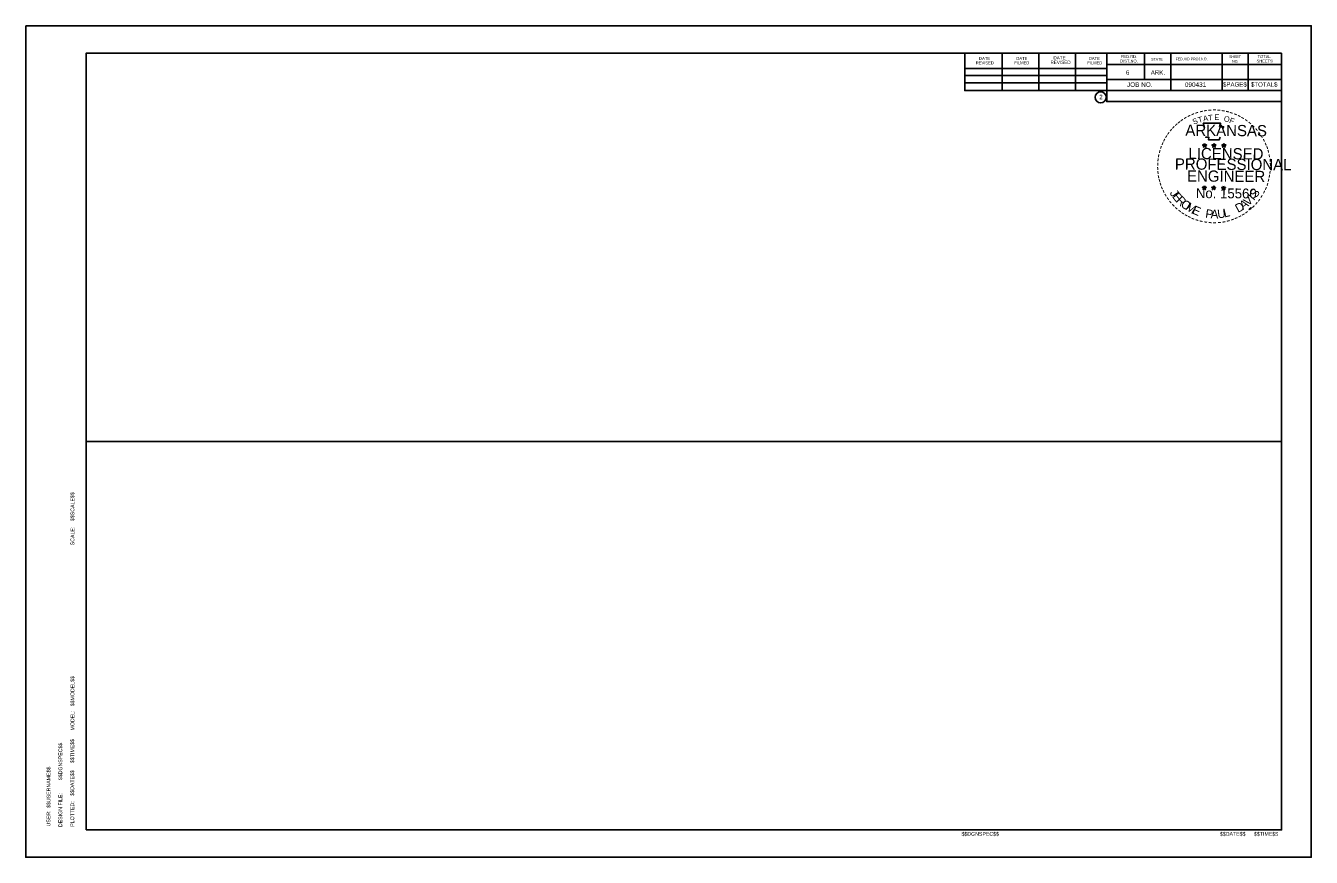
# Model space of a CAD drawing. Extents: x -1.6 to 32.4, y -0.7 to 21.3.
import ezdxf

# ---------------------------------------------------------------- set-up
doc = ezdxf.new("R2010")
doc.units = 0
for name, color, linetype in [('Level 1', 7, 'Continuous'), ('Level 24', 7, 'Continuous'), ('Level 37', 7, 'Continuous'), ('Level 48', 7, 'Continuous'), ('Level 62', 7, 'Continuous'), ('Level 63', 7, 'Continuous'), ('R_Border Prelim', 7, 'Continuous')]:
    doc.layers.add(name, color=color, linetype=linetype)

msp = doc.modelspace()

# ---------------------------------------------------------------- linework, layer by layer
at = {"layer": 'Level 1'}
for p, q in [((-0.001, 20.545), (31.617, 20.545)), ((-0.001, -0.001), (-0.001, 20.545)), ((23.238, 19.557), (23.238, 20.545)), ((24.224, 19.557), (24.224, 20.525)), ((25.2, 19.557), (25.2, 20.525)), ((26.168, 19.557), (26.168, 20.525)), ((26.994, 20.545), (26.994, 19.557)), ((27.991, 20.545), (27.991, 19.851)), ((28.685, 20.545), (28.685, 19.557)), ((30.043, 20.545), (30.043, 19.557)), ((30.737, 20.545), (30.737, 19.557)), ((31.617, -0.001), (31.617, 20.545)), ((23.238, 20.143), (26.994, 20.143)), ((31.617, 20.251), (26.994, 20.251)), ((31.617, 20.253), (31.617, 20.253)), ((23.238, 19.957), (26.994, 19.957)), ((23.238, 19.763), (26.994, 19.763)), ((31.617, 19.851), (26.994, 19.851)), ((27.603, 19.851), (31.617, 19.851)), ((31.617, 19.557), (23.238, 19.557)), ((26.994, 19.557), (26.994, 19.265)), ((26.994, 19.265), (31.617, 19.265)), ((31.617, -0.001), (-0.001, -0.001))]:
    msp.add_line(p, q, dxfattribs=at)
msp.add_circle((26.833, 19.379), 0.147, dxfattribs=at)
at = {"layer": 'Level 24'}
for p, q in [((-0.001, 20.545), (-0.001, -0.001)), ((23.238, 19.557), (23.238, 20.545)), ((26.999, 19.557), (23.238, 19.557)), ((26.994, 19.265), (26.994, 19.557)), ((26.994, 19.557), (26.999, 19.557)), ((31.617, 19.265), (26.994, 19.265)), ((26.994, 19.265), (26.994, 19.265)), ((31.617, -0.001), (31.617, 19.265)), ((-0.001, -0.001), (31.617, -0.001))]:
    msp.add_line(p, q, dxfattribs=at)
msp.add_lwpolyline([(23.238, 20.545), (23.391, 20.545), (23.391, 20.545), (-0.001, 20.545)], dxfattribs=at)
at = {"layer": 'Level 37'}
for p, q in [((-0.002, 10.755), (-0.001, 20.545)), ((-0.001, 20.545), (31.617, 20.545)), ((31.617, 20.545), (31.617, 10.273)), ((-0.001, 10.273), (-0.002, 10.755)), ((-0.002, 10.755), (-0.002, 10.755)), ((-0.002, 0.481), (-0.001, 10.271)), ((-0.002, 0.481), (-0.001, 10.271)), ((31.617, 10.273), (-0.001, 10.273)), ((-0.001, 10.271), (31.617, 10.271)), ((-0.001, 10.271), (31.617, 10.271)), ((31.617, 10.271), (31.617, -0.001)), ((31.617, 10.271), (31.617, -0.001)), ((-0.001, -0.001), (-0.002, 0.481)), ((-0.002, 0.481), (-0.002, 0.481)), ((-0.001, -0.001), (-0.002, 0.481)), ((-0.002, 0.481), (-0.002, 0.481)), ((31.617, -0.001), (-0.001, -0.001)), ((31.617, -0.001), (-0.001, -0.001))]:
    msp.add_line(p, q, dxfattribs=at)
at = {"layer": 'Level 62'}
msp.add_lwpolyline([(-0.001, -0.001), (31.617, -0.001), (31.617, 19.265), (26.994, 19.265), (26.994, 19.557), (27.307, 19.557), (26.999, 19.557), (23.238, 19.557), (23.238, 20.545), (23.391, 20.545), (23.391, 20.545), (-0.001, 20.545)], close=True, dxfattribs=at)
at = {"layer": 'Level 63'}
msp.add_lwpolyline([(-1.598, 21.273), (32.402, 21.273), (32.402, -0.727), (-1.598, -0.727)], close=True, dxfattribs=at)
at = {"layer": 'R_Border Prelim'}
for p, q in [((29.529, 18.121), (29.582, 18.105)), ((29.529, 18.121), (29.567, 18.119)), ((29.529, 18.121), (29.567, 18.117)), ((29.529, 18.121), (29.564, 18.112)), ((29.529, 18.121), (29.564, 18.106)), ((29.529, 18.121), (29.564, 18.105)), ((29.529, 18.121), (29.564, 18.099)), ((29.551, 18.061), (29.582, 18.105)), ((29.551, 18.061), (29.564, 18.103)), ((29.551, 18.061), (29.567, 18.097)), ((29.551, 18.061), (29.569, 18.095)), ((29.551, 18.061), (29.575, 18.092)), ((29.551, 18.061), (29.582, 18.092)), ((29.551, 18.061), (29.582, 18.088)), ((29.582, 18.161), (29.575, 18.121)), ((29.582, 18.161), (29.575, 18.125)), ((29.582, 18.161), (29.578, 18.125)), ((29.582, 18.105), (29.582, 18.161)), ((29.582, 18.161), (29.591, 18.121)), ((29.582, 18.161), (29.589, 18.125)), ((29.582, 18.161), (29.584, 18.125)), ((29.633, 18.121), (29.582, 18.105)), ((29.613, 18.059), (29.582, 18.105)), ((29.613, 18.059), (29.582, 18.092)), ((29.613, 18.059), (29.582, 18.088)), ((29.633, 18.121), (29.586, 18.117)), ((29.613, 18.059), (29.586, 18.092)), ((29.633, 18.121), (29.591, 18.114)), ((29.633, 18.121), (29.591, 18.11)), ((29.613, 18.059), (29.591, 18.103)), ((29.613, 18.059), (29.591, 18.097)), ((29.613, 18.059), (29.597, 18.105)), ((29.633, 18.121), (29.598, 18.11)), ((29.633, 18.121), (29.604, 18.106)), ((29.633, 18.121), (29.606, 18.105)), ((29.776, 18.119), (29.829, 18.105)), ((29.776, 18.119), (29.814, 18.117)), ((29.776, 18.119), (29.814, 18.114)), ((29.776, 18.119), (29.814, 18.112)), ((29.776, 18.119), (29.813, 18.105)), ((29.776, 18.119), (29.813, 18.103)), ((29.776, 18.119), (29.813, 18.097)), ((29.798, 18.059), (29.829, 18.105)), ((29.798, 18.059), (29.814, 18.099)), ((29.798, 18.059), (29.814, 18.097)), ((29.798, 18.059), (29.816, 18.095)), ((29.798, 18.059), (29.822, 18.09)), ((29.798, 18.059), (29.829, 18.09)), ((29.798, 18.059), (29.829, 18.088)), ((29.829, 18.158), (29.822, 18.119)), ((29.829, 18.158), (29.822, 18.121)), ((29.829, 18.158), (29.824, 18.121)), ((29.829, 18.105), (29.829, 18.158)), ((29.829, 18.158), (29.838, 18.119)), ((29.829, 18.158), (29.836, 18.121)), ((29.829, 18.158), (29.831, 18.121)), ((29.88, 18.119), (29.829, 18.105)), ((29.86, 18.059), (29.829, 18.105)), ((29.86, 18.059), (29.829, 18.09)), ((29.86, 18.059), (29.829, 18.088)), ((29.88, 18.119), (29.834, 18.117)), ((29.86, 18.059), (29.834, 18.09)), ((29.88, 18.119), (29.838, 18.112)), ((29.88, 18.119), (29.838, 18.11)), ((29.86, 18.059), (29.838, 18.103)), ((29.86, 18.059), (29.838, 18.095)), ((29.86, 18.059), (29.844, 18.103)), ((29.88, 18.119), (29.845, 18.106)), ((29.88, 18.119), (29.851, 18.105)), ((29.88, 18.119), (29.853, 18.103)), ((30.038, 18.117), (30.091, 18.099)), ((30.038, 18.117), (30.08, 18.112)), ((30.038, 18.117), (30.076, 18.11)), ((30.038, 18.117), (30.076, 18.106)), ((30.038, 18.117), (30.074, 18.103)), ((30.038, 18.117), (30.074, 18.097)), ((30.038, 18.117), (30.074, 18.097)), ((30.058, 18.057), (30.091, 18.099)), ((30.058, 18.057), (30.076, 18.097)), ((30.058, 18.057), (30.08, 18.092)), ((30.058, 18.057), (30.08, 18.09)), ((30.058, 18.057), (30.091, 18.09)), ((30.058, 18.057), (30.087, 18.088)), ((30.058, 18.057), (30.094, 18.083)), ((30.091, 18.154), (30.081, 18.119)), ((30.091, 18.154), (30.087, 18.117)), ((30.091, 18.154), (30.087, 18.117)), ((30.091, 18.099), (30.091, 18.154)), ((30.091, 18.154), (30.102, 18.117)), ((30.091, 18.154), (30.098, 18.117)), ((30.091, 18.154), (30.094, 18.117)), ((30.142, 18.117), (30.091, 18.099)), ((30.12, 18.057), (30.091, 18.099)), ((30.12, 18.057), (30.091, 18.09)), ((30.12, 18.057), (30.091, 18.083)), ((30.142, 18.117), (30.096, 18.112)), ((30.12, 18.057), (30.096, 18.088)), ((30.142, 18.117), (30.102, 18.11)), ((30.142, 18.117), (30.102, 18.105)), ((30.12, 18.057), (30.102, 18.097)), ((30.12, 18.057), (30.102, 18.092)), ((30.12, 18.057), (30.105, 18.097)), ((30.142, 18.117), (30.109, 18.103)), ((30.142, 18.117), (30.111, 18.103)), ((30.142, 18.117), (30.116, 18.099)), ((29.575, 17.038), (29.564, 17.001)), ((29.575, 17.038), (29.567, 16.998)), ((29.575, 17.038), (29.569, 16.998)), ((29.575, 16.981), (29.575, 17.038)), ((29.575, 17.038), (29.582, 16.998)), ((29.575, 17.038), (29.582, 16.998)), ((29.575, 17.038), (29.575, 16.998)), ((29.822, 17.034), (29.813, 16.998)), ((29.822, 17.034), (29.814, 16.998)), ((29.822, 17.034), (29.816, 16.998)), ((29.822, 16.981), (29.822, 17.034)), ((29.822, 17.034), (29.829, 16.996)), ((29.822, 17.034), (29.829, 16.996)), ((29.822, 17.034), (29.822, 16.998)), ((30.083, 17.032), (30.074, 16.994)), ((30.083, 17.032), (30.076, 16.994)), ((30.083, 17.032), (30.08, 16.994)), ((30.083, 16.976), (30.083, 17.032)), ((30.083, 17.032), (30.091, 16.994)), ((30.083, 17.032), (30.091, 16.994)), ((30.083, 17.032), (30.083, 16.994)), ((29.522, 16.998), (29.575, 16.981)), ((29.522, 16.998), (29.56, 16.996)), ((29.522, 16.998), (29.558, 16.99)), ((29.522, 16.998), (29.558, 16.99)), ((29.522, 16.998), (29.558, 16.983)), ((29.522, 16.998), (29.558, 16.981)), ((29.522, 16.998), (29.558, 16.979)), ((29.54, 16.941), (29.575, 16.981)), ((29.54, 16.941), (29.558, 16.981)), ((29.54, 16.941), (29.56, 16.974)), ((29.54, 16.941), (29.562, 16.974)), ((29.54, 16.941), (29.575, 16.972)), ((29.54, 16.941), (29.567, 16.968)), ((29.54, 16.941), (29.575, 16.967)), ((29.604, 16.937), (29.571, 16.967)), ((29.626, 16.998), (29.575, 16.981)), ((29.604, 16.937), (29.575, 16.981)), ((29.604, 16.937), (29.575, 16.968)), ((29.604, 16.937), (29.577, 16.968)), ((29.626, 16.998), (29.578, 16.996)), ((29.626, 16.998), (29.582, 16.99)), ((29.626, 16.998), (29.582, 16.989)), ((29.604, 16.937), (29.582, 16.981)), ((29.604, 16.937), (29.582, 16.974)), ((29.626, 16.998), (29.589, 16.987)), ((29.604, 16.937), (29.589, 16.981)), ((29.626, 16.998), (29.593, 16.983)), ((29.626, 16.998), (29.597, 16.981)), ((29.769, 16.998), (29.822, 16.981)), ((29.769, 16.998), (29.807, 16.994)), ((29.769, 16.998), (29.807, 16.99)), ((29.769, 16.998), (29.807, 16.989)), ((29.769, 16.998), (29.805, 16.983)), ((29.769, 16.998), (29.805, 16.979)), ((29.769, 16.998), (29.805, 16.976)), ((29.787, 16.937), (29.822, 16.981)), ((29.787, 16.937), (29.807, 16.979)), ((29.787, 16.937), (29.807, 16.972)), ((29.787, 16.937), (29.809, 16.972)), ((29.787, 16.937), (29.814, 16.968)), ((29.787, 16.937), (29.822, 16.968)), ((29.787, 16.937), (29.822, 16.965)), ((29.851, 16.937), (29.82, 16.965)), ((29.871, 16.996), (29.822, 16.981)), ((29.851, 16.937), (29.822, 16.981)), ((29.851, 16.937), (29.822, 16.968)), ((29.851, 16.937), (29.824, 16.968)), ((29.871, 16.996), (29.827, 16.996)), ((29.871, 16.996), (29.829, 16.989)), ((29.871, 16.996), (29.829, 16.989)), ((29.851, 16.937), (29.829, 16.979)), ((29.851, 16.937), (29.829, 16.974)), ((29.871, 16.996), (29.836, 16.983)), ((29.851, 16.937), (29.836, 16.979)), ((29.871, 16.996), (29.842, 16.981)), ((29.871, 16.996), (29.844, 16.979)), ((30.03, 16.994), (30.083, 16.976)), ((30.03, 16.994), (30.069, 16.99)), ((30.03, 16.994), (30.069, 16.987)), ((30.03, 16.994), (30.067, 16.983)), ((30.03, 16.994), (30.067, 16.979)), ((30.03, 16.994), (30.065, 16.976)), ((30.03, 16.994), (30.065, 16.972)), ((30.05, 16.934), (30.083, 16.976)), ((30.05, 16.934), (30.067, 16.976)), ((30.05, 16.934), (30.069, 16.968)), ((30.05, 16.934), (30.072, 16.968)), ((30.05, 16.934), (30.076, 16.965)), ((30.05, 16.934), (30.081, 16.965)), ((30.05, 16.934), (30.083, 16.961)), ((30.113, 16.934), (30.081, 16.965)), ((30.113, 16.934), (30.081, 16.961)), ((30.135, 16.994), (30.083, 16.976)), ((30.113, 16.934), (30.083, 16.976)), ((30.113, 16.934), (30.087, 16.965)), ((30.135, 16.994), (30.089, 16.99)), ((30.135, 16.994), (30.091, 16.987)), ((30.135, 16.994), (30.091, 16.983)), ((30.113, 16.934), (30.091, 16.968)), ((30.113, 16.934), (30.094, 16.976)), ((30.113, 16.934), (30.096, 16.976)), ((30.135, 16.994), (30.102, 16.981)), ((30.135, 16.994), (30.103, 16.976)), ((30.135, 16.994), (30.105, 16.976))]:
    msp.add_line(p, q, dxfattribs=at)
for points in [[(29.54, 18.697), (29.577, 18.573)], [(30.06, 18.556), (30.081, 18.6), (29.977, 18.595), (30.001, 18.694), (29.54, 18.697)], [(29.582, 18.161), (29.613, 18.059), (29.529, 18.121), (29.633, 18.121), (29.551, 18.061), (29.582, 18.161)], [(29.611, 18.337), (29.611, 18.322), (29.694, 18.32), (29.686, 18.253), (29.963, 18.251), (29.992, 18.328)], [(29.829, 18.158), (29.86, 18.059), (29.776, 18.119), (29.88, 18.119), (29.798, 18.059), (29.829, 18.158)], [(30.091, 18.154), (30.12, 18.057), (30.038, 18.117), (30.142, 18.117), (30.058, 18.057), (30.091, 18.154)], [(29.575, 17.038), (29.604, 16.937), (29.522, 16.998), (29.626, 16.998), (29.54, 16.941), (29.575, 17.038)], [(29.822, 17.034), (29.851, 16.937), (29.769, 16.998), (29.871, 16.996), (29.787, 16.937), (29.822, 17.034)], [(30.083, 17.032), (30.113, 16.934), (30.03, 16.994), (30.135, 16.994), (30.05, 16.934), (30.083, 17.032)], [(30.769, 16.4), (30.762, 16.423), (30.806, 16.46)], [(30.802, 16.465), (30.81, 16.443), (30.766, 16.405)], [(30.81, 16.447), (30.766, 16.409)], [(30.81, 16.443), (30.767, 16.407)]]:
    msp.add_lwpolyline(points, dxfattribs=at)
for centre, radius in [((29.583, 18.104), 0.0255), ((29.583, 18.104), 0.0231), ((29.583, 18.104), 0.0214), ((29.583, 18.104), 0.0197), ((29.583, 18.104), 0.0172), ((29.583, 18.104), 0.0159), ((29.583, 18.104), 0.0147), ((29.583, 18.104), 0.0126), ((29.583, 18.104), 0.0111), ((29.583, 18.104), 0.00921), ((29.583, 18.104), 0.00734), ((29.583, 18.104), 0.00548), ((29.583, 18.104), 0.00439), ((29.583, 18.104), 0.00214), ((29.83, 18.102), 0.0255), ((29.83, 18.102), 0.0231), ((29.83, 18.102), 0.0214), ((29.83, 18.102), 0.0197), ((29.83, 18.102), 0.0172), ((29.83, 18.102), 0.0159), ((29.83, 18.102), 0.0147), ((29.83, 18.102), 0.0126), ((29.83, 18.102), 0.0111), ((29.83, 18.102), 0.00921), ((29.83, 18.102), 0.00734), ((29.83, 18.102), 0.00548), ((29.83, 18.102), 0.00439), ((29.83, 18.102), 0.00214), ((30.092, 18.098), 0.0255), ((30.092, 18.098), 0.0231), ((30.092, 18.098), 0.0214), ((30.092, 18.098), 0.0197), ((30.092, 18.098), 0.0172), ((30.092, 18.098), 0.0159), ((30.092, 18.098), 0.0147), ((30.092, 18.098), 0.0126), ((30.092, 18.098), 0.0111), ((30.092, 18.098), 0.00921), ((30.092, 18.098), 0.00734), ((30.092, 18.098), 0.00548), ((30.092, 18.098), 0.00439), ((30.092, 18.098), 0.00214), ((29.575, 16.981), 0.0255), ((29.575, 16.981), 0.0231), ((29.575, 16.981), 0.0214), ((29.575, 16.981), 0.0197), ((29.822, 16.979), 0.0255), ((29.822, 16.979), 0.0231), ((29.822, 16.979), 0.0214), ((30.084, 16.976), 0.0255), ((29.575, 16.981), 0.0172), ((29.575, 16.981), 0.0159), ((29.575, 16.981), 0.0147), ((29.575, 16.981), 0.0126), ((29.575, 16.981), 0.0111), ((29.575, 16.981), 0.00921), ((29.575, 16.981), 0.00734), ((29.575, 16.981), 0.00548), ((29.575, 16.981), 0.00439), ((29.575, 16.981), 0.00214), ((29.822, 16.979), 0.0197), ((29.822, 16.979), 0.0172), ((29.822, 16.979), 0.0159), ((29.822, 16.979), 0.0147), ((29.822, 16.979), 0.0126), ((29.822, 16.979), 0.0111), ((29.822, 16.979), 0.00921), ((29.822, 16.979), 0.00734), ((29.822, 16.979), 0.00548), ((29.822, 16.979), 0.00439), ((29.822, 16.979), 0.00214), ((30.084, 16.976), 0.0231), ((30.084, 16.976), 0.0214), ((30.084, 16.976), 0.0197), ((30.084, 16.976), 0.0172), ((30.084, 16.976), 0.0159), ((30.084, 16.976), 0.0147), ((30.084, 16.976), 0.0126), ((30.084, 16.976), 0.0111), ((30.084, 16.976), 0.00921), ((30.084, 16.976), 0.00734), ((30.084, 16.976), 0.00548), ((30.084, 16.976), 0.00439), ((30.084, 16.976), 0.00214)]:
    msp.add_circle(centre, radius, dxfattribs=at)

# ---------------------------------------------------------------- texts
at = {"layer": 'Level 1'}
for s, height, p in [('DATE', 0.0782, (23.618, 20.369)), ('DATE', 0.0782, (24.604, 20.369)), ('DATE', 0.0879, (25.582, 20.379)), ('DATE', 0.0782, (26.52, 20.369)), ('FED.RD.', 0.0782, (27.366, 20.417)), ('STATE', 0.0684, (28.167, 20.349)), ('FED.AID PROJ.NO.', 0.0684, (28.813, 20.359)), ('SHEET', 0.0684, (30.229, 20.417)), ('TOTAL', 0.0782, (30.981, 20.417)), ('REVISED', 0.0782, (23.53, 20.251)), ('FILMED', 0.0782, (24.546, 20.251)), ('REVISED', 0.0879, (25.504, 20.261)), ('FILMED', 0.0782, (26.48, 20.251)), ('DIST.NO.', 0.0782, (27.346, 20.299)), ('6', 0.117, (27.501, 19.977)), ('ARK.', 0.1172, (28.157, 19.977)), ('NO.', 0.0684, (30.307, 20.299)), ('SHEETS', 0.0782, (30.953, 20.299)), ('JOB NO.', 0.1224, (27.528, 19.653)), ('090431', 0.1224, (29.059, 19.653)), ('$PAGE$', 0.1172, (30.067, 19.66)), ('$TOTAL$', 0.1172, (30.806, 19.66)), ('2', 0.117, (26.795, 19.329))]:
    msp.add_text(s, height=height, dxfattribs=at).set_placement(p)
for s, p in [('$$SCALE$$', (-0.313, 8.169)), ('SCALE:', (-0.313, 7.528)), ('$$MODEL$$', (-0.313, 3.269)), ('MODEL:', (-0.313, 2.628)), ('$$TIME$$', (-0.316, 1.767)), ('$$DGNSPEC$$', (-0.632, 1.314)), ('$$USERNAME$$', (-0.944, 0.58)), ('$$DATE$$', (-0.316, 0.903)), ('DESIGN FILE:', (-0.632, 0.073)), ('PLOTTED:', (-0.316, 0.081)), ('USER:', (-0.948, 0.089))]:
    msp.add_text(s, height=0.1, rotation=90, dxfattribs=at).set_placement(p)
at = {"layer": 'Level 48'}
for s, p in [('$$DGNSPEC$$', (23.152, -0.159)), ('$$DATE$$', (29.986, -0.159)), ('$$TIME$$', (30.887, -0.159))]:
    msp.add_text(s, height=0.1, dxfattribs=at).set_placement(p)
at = {"layer": 'R_Border Prelim'}
for s, height, rotation, p in [('-', 0.237, 9.8217, (29.564, 18.926)), ('-', 0.237, 5.4992, (29.673, 18.941)), ('-', 0.237, 359.7886, (29.787, 18.952)), ('-', 0.237, 357.3454, (29.897, 18.948)), ('-', 0.237, 351.7641, (30.005, 18.939)), ('-', 0.237, 38.5531, (28.92, 18.613)), ('-', 0.237, 35.8341, (28.989, 18.67)), ('-', 0.237, 33.666, (29.075, 18.728)), ('-', 0.237, 28.3942, (29.165, 18.781)), ('-', 0.237, 23.9096, (29.258, 18.827)), ('S', 0.148, 21.1964, (29.293, 18.652)), ('-', 0.237, 18.7785, (29.353, 18.867)), ('T', 0.148, 16.006, (29.428, 18.701)), ('-', 0.237, 13.2326, (29.465, 18.902)), ('A', 0.148, 10.8156, (29.553, 18.738)), ('T', 0.148, 5.6252, (29.679, 18.761)), ('E', 0.148, 0.4347, (29.842, 18.776)), ('O', 0.148, 350.0539, (30.08, 18.745)), ('-', 0.237, 346.8073, (30.113, 18.922)), ('F', 0.148, 339.6731, (30.22, 18.708)), ('-', 0.237, 341.9386, (30.206, 18.897)), ('-', 0.237, 337.4575, (30.314, 18.864)), ('-', 0.237, 333.7235, (30.409, 18.825)), ('-', 0.237, 329.2433, (30.493, 18.781)), ('-', 0.237, 325.4651, (30.588, 18.725)), ('-', 0.237, 320.1321, (30.678, 18.662)), ('-', 0.237, 57.673, (28.616, 18.247)), ('-', 0.237, 53.8349, (28.664, 18.328)), ('-', 0.237, 50.2166, (28.726, 18.412)), ('-', 0.237, 48.0254, (28.786, 18.483)), ('-', 0.237, 42.5646, (28.854, 18.553)), ('ARKANSAS', 0.2964, 359.6024, (29.07, 18.361)), ('-', 0.237, 315.181, (30.767, 18.589)), ('-', 0.237, 309.4821, (30.85, 18.507)), ('-', 0.237, 306.2546, (30.925, 18.417)), ('-', 0.207, 303.2777, (30.998, 18.331)), ('-', 0.237, 71.9969, (28.497, 17.975)), ('-', 0.237, 67.3767, (28.532, 18.068)), ('-', 0.237, 62.4738, (28.57, 18.158)), ('LICENSED', 0.2964, 359.6024, (29.153, 17.746)), ('-', 0.237, 299.2708, (31.044, 18.242)), ('-', 0.237, 294.2652, (31.091, 18.15)), ('-', 0.237, 290.1752, (31.132, 18.068)), ('-', 0.237, 84.7887, (28.435, 17.662)), ('-', 0.237, 80.8037, (28.446, 17.764)), ('-', 0.237, 75.0634, (28.468, 17.869)), ('PROFESSIONAL', 0.29643, 359.6024, (28.794, 17.468)), ('-', 0.237, 284.7257, (31.163, 17.98)), ('-', 0.237, 280.1517, (31.192, 17.869)), ('-', 0.237, 276.1986, (31.218, 17.755)), ('-', 0.237, 93.7983, (28.435, 17.45)), ('-', 0.237, 88.6646, (28.431, 17.558)), ('-', 0.237, 98.5503, (28.446, 17.349)), ('ENGINEER', 0.2964, 359.6024, (29.114, 17.151)), ('-', 0.237, 263.1196, (31.225, 17.457)), ('-', 0.237, 273.9325, (31.225, 17.647)), ('-', 0.237, 269.5431, (31.229, 17.556)), ('-', 0.237, 101.3173, (28.462, 17.241)), ('-', 0.237, 105.0602, (28.488, 17.153)), ('-', 0.237, 108.6898, (28.519, 17.062)), ('-', 0.237, 113.6667, (28.556, 16.97)), ('-', 0.237, 247.4911, (31.137, 17.051)), ('-', 0.237, 252.4705, (31.17, 17.151)), ('-', 0.237, 255.365, (31.196, 17.259)), ('-', 0.237, 260.5977, (31.212, 17.36)), ('-', 0.237, 115.3313, (28.601, 16.879)), ('-', 0.237, 120.0495, (28.653, 16.791)), ('-', 0.237, 125.4958, (28.713, 16.709)), ('J', 0.228, 303.9209, (28.647, 16.844)), ('E', 0.228, 308.618, (28.711, 16.748)), ('R', 0.228, 314.7784, (28.807, 16.631)), ('No. 15560', 0.2608, 359.6024, (29.348, 16.713)), ('V', 0.228, 41.4844, (30.73, 16.49)), ('I', 0.228, 49.9999, (30.881, 16.633)), ('S', 0.228, 53.5227, (30.938, 16.699)), ('-', 0.237, 233.4476, (30.98, 16.753)), ('-', 0.237, 238.6736, (31.036, 16.85)), ('-', 0.237, 244.2221, (31.095, 16.959)), ('-', 0.237, 130.3205, (28.779, 16.626)), ('-', 0.237, 133.8262, (28.856, 16.546)), ('-', 0.237, 138.5362, (28.931, 16.476)), ('-', 0.237, 144.2487, (29.017, 16.416)), ('-', 0.237, 147.6922, (29.097, 16.359)), ('O', 0.228, 321.6761, (28.928, 16.514)), ('M', 0.228, 328.1357, (29.054, 16.418)), ('E', 0.228, 336.4966, (29.231, 16.315)), ('P', 0.228, 351.9783, (29.59, 16.197)), ('A', 0.228, 357.9896, (29.737, 16.179)), ('U', 0.228, 5.7635, (29.927, 16.177)), ('L', 0.228, 13.0992, (30.105, 16.199)), ('D', 0.228, 28.5809, (30.464, 16.319)), ('A', 0.228, 34.8903, (30.599, 16.395)), ('-', 0.237, 215.3387, (30.68, 16.442)), ('-', 0.237, 225.3677, (30.841, 16.586)), ('-', 0.237, 233.4476, (30.91, 16.672)), ('-', 0.237, 151.1728, (29.181, 16.312)), ('-', 0.237, 154.2026, (29.262, 16.273)), ('-', 0.237, 158.1636, (29.353, 16.233)), ('-', 0.237, 162.4007, (29.456, 16.202)), ('-', 0.237, 167.1579, (29.56, 16.178)), ('-', 0.237, 172.7179, (29.673, 16.162)), ('-', 0.237, 176.1207, (29.785, 16.151)), ('-', 0.237, 181.1942, (29.895, 16.154)), ('-', 0.237, 185.4191, (30.016, 16.164)), ('-', 0.237, 190.8882, (30.125, 16.182)), ('-', 0.237, 195.0767, (30.233, 16.211)), ('-', 0.237, 200.3208, (30.334, 16.248)), ('-', 0.237, 203.854, (30.425, 16.288)), ('-', 0.237, 206.9592, (30.519, 16.334)), ('-', 0.237, 211.8515, (30.601, 16.385))]:
    msp.add_text(s, height=height, rotation=rotation, dxfattribs=at).set_placement(p)

doc.saveas('drawing.dxf')
